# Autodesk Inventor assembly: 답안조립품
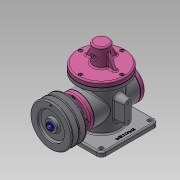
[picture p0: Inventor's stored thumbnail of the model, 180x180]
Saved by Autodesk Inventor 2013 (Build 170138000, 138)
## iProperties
Created: 2020-02
Part Number: 답안조립품
Document SubType Name: Assembly
Designer: Administrator
Author: Administrator
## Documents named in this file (21)
- C:\Users\Administrator\Desktop\600206v1018\답안조립품.iam
- C:\Users\Administrator\Desktop\600206v1018\본체.ipt
- C:\Users\Administrator\Desktop\600206v1018\E-링.ipt
- C:\Users\Administrator\Desktop\600206v1018\V-벨트풀리.ipt
- C:\Users\Administrator\Desktop\600206v1018\가변스프링.ipt
- C:\Users\Administrator\Desktop\600206v1018\개스킷 A.ipt
- C:\Users\Administrator\Desktop\600206v1018\개스킷 B.ipt
- C:\Users\Administrator\Desktop\600206v1018\덮개.ipt
- C:\Users\Administrator\Desktop\600206v1018\뒤커버.ipt
- C:\Users\Administrator\Desktop\600206v1018\링크.ipt
- C:\Users\Administrator\Desktop\600206v1018\베어링 17 x 40 x 12.ipt
- C:\Users\Administrator\Desktop\600206v1018\볼트 M4 x 10.ipt
- C:\Users\Administrator\Desktop\600206v1018\슬라이더.ipt
- C:\Users\Administrator\Desktop\600206v1018\앞커버.ipt
- C:\Users\Administrator\Desktop\600206v1018\오일 실 17 30 8.ipt
- C:\Users\Administrator\Desktop\600206v1018\와셔 4x16.ipt
- C:\Users\Administrator\Desktop\600206v1018\육각 소켓 머리 볼트 M4 x 10.ipt
- C:\Users\Administrator\Desktop\600206v1018\클레비스 핀 6 x 22.ipt
- 클레비스 핀 6 x 22.ipt
- C:\Users\Administrator\Desktop\600206v1018\키 4 x 4 x 25.ipt
- C:\Users\Administrator\Desktop\600206v1018\편심축.ipt
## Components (6 placed, 5 different names)
1. E-링:1 — 각도:2
2. V-벨트풀리:1 — 플러쉬:1
3. 가변스프링:1
4. 개스킷 A:1
5. 개스킷 B:1
6. 개스킷 A:2
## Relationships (2: Flush 1, Angle 1)
- 플러쉬:1 [Flush]: V-벨트풀리:1
- 각도:2 [Angle]: E-링:1
